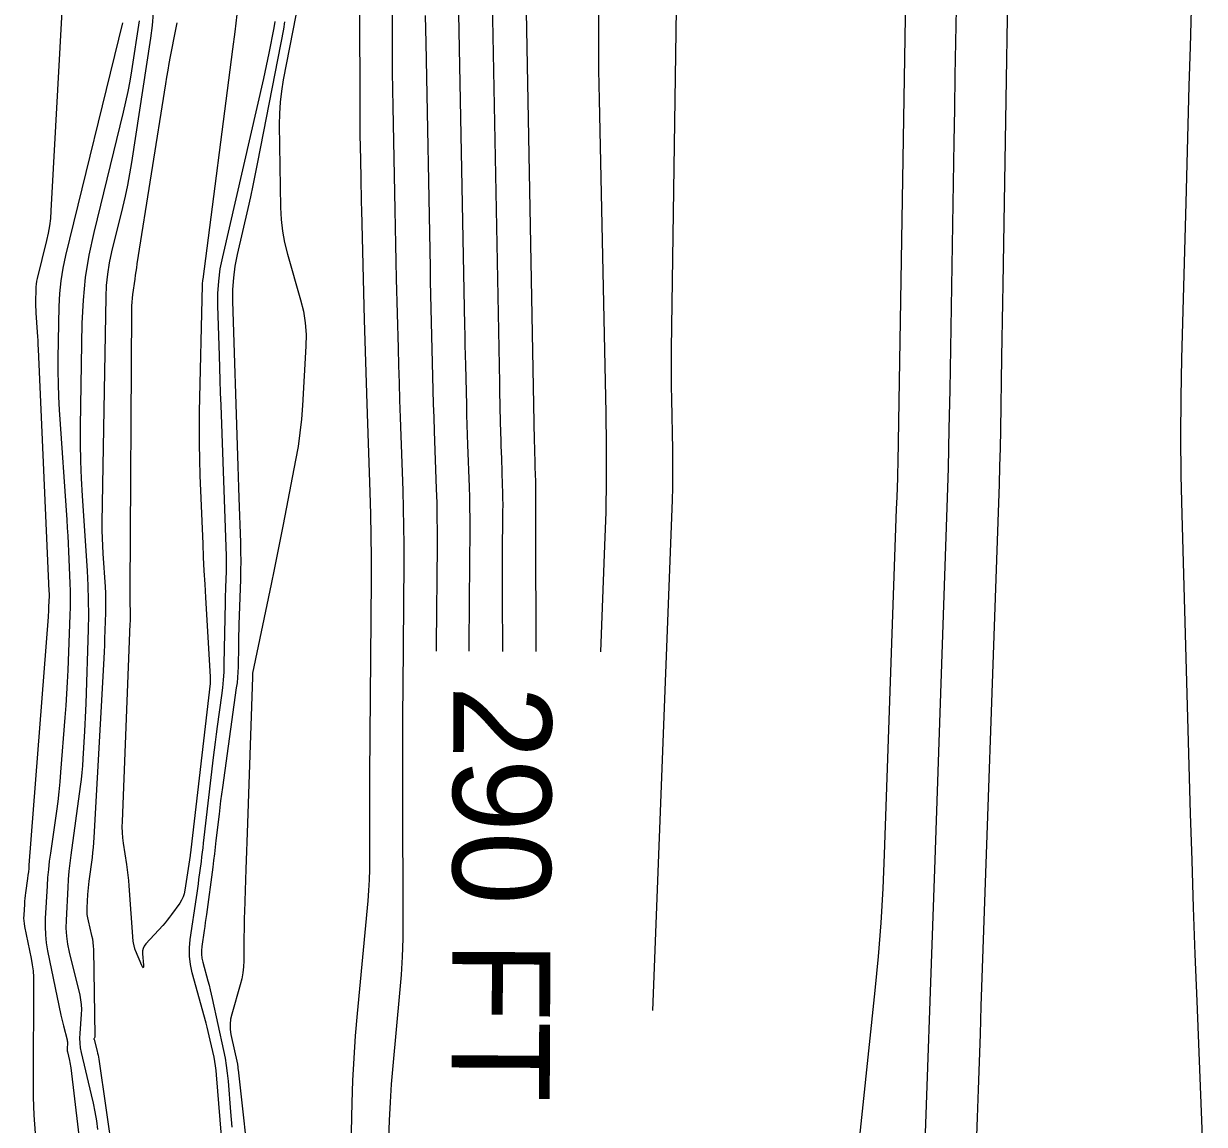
# Model space of a CAD drawing. Extents: x 1768942 to 1774819, y 723037 to 732099.
# Drawn here: x 1770862.5 to 1770934.6, y 724105.6 to 724172.9 of the extents above; entities that cross this region are included whole.
import ezdxf

# ---------------------------------------------------------------- set-up
doc = ezdxf.new("R2010")
doc.units = 0
doc.layers.add('R_Contour Annot', color=7, linetype='Continuous')
doc.layers.add('R_Contours', color=7, linetype='Continuous')

msp = doc.modelspace()

# ---------------------------------------------------------------- linework, layer by layer
at = {"layer": 'R_Contours'}
for points in [[(1770902.56, 724186.241), (1770902.065, 724153.005), (1770902.057, 724152.234), (1770902.056, 724151.462), (1770902.062, 724150.691), (1770902.075, 724149.92), (1770902.14, 724146.835), (1770902.151, 724146.064), (1770902.15, 724145.293), (1770902.138, 724144.522), (1770902.114, 724143.751), (1770900.92, 724112.576)], [(1770922.804, 724185.752), (1770922.328, 724156.942), (1770922.309, 724155.83), (1770922.291, 724154.718), (1770922.273, 724153.606), (1770922.254, 724152.494), (1770922.18, 724148.046), (1770922.158, 724146.934), (1770922.132, 724145.823), (1770922.101, 724144.711), (1770922.065, 724143.6), (1770920.995, 724112.825), (1770920.936, 724111.128), (1770920.877, 724109.431), (1770920.818, 724107.734), (1770920.759, 724106.037), (1770920.523, 724099.249)], [(1770916.552, 724184.367), (1770915.911, 724146.07), (1770915.907, 724145.832), (1770915.901, 724145.594), (1770915.894, 724145.357), (1770915.887, 724145.119), (1770915.845, 724143.931), (1770915.821, 724143.219), (1770915.086, 724122.095), (1770914.996, 724120.014), (1770914.87, 724117.935), (1770914.707, 724115.859), (1770914.509, 724113.785), (1770913.356, 724102.74)], [(1770934.646, 724101.684), (1770934.196, 724113.142), (1770934.087, 724116.007), (1770933.986, 724118.872), (1770933.892, 724121.737), (1770933.806, 724124.603), (1770933.28, 724142.88), (1770933.228, 724145.261), (1770933.21, 724147.642), (1770933.224, 724150.023), (1770933.271, 724152.405), (1770933.527, 724161.931), (1770933.592, 724164.312), (1770933.657, 724166.692), (1770933.722, 724169.073), (1770933.789, 724171.453), (1770934.152, 724184.435)], [(1770893.812, 724134.504), (1770893.787, 724141.931), (1770893.786, 724142.182), (1770893.787, 724142.433), (1770893.788, 724142.684), (1770893.789, 724142.935), (1770893.798, 724144.104), (1770893.799, 724144.272), (1770893.797, 724144.44), (1770893.794, 724144.607), (1770893.789, 724144.775), (1770893.765, 724145.458), (1770893.759, 724145.619), (1770893.754, 724145.781), (1770893.749, 724145.942), (1770893.745, 724146.104), (1770893.729, 724146.751), (1770893.725, 724146.912), (1770893.721, 724147.074), (1770893.718, 724147.235), (1770893.715, 724147.397), (1770893.031, 724183.449)], [(1770891.767, 724134.514), (1770891.756, 724137.881), (1770891.755, 724138.48), (1770891.756, 724139.078), (1770891.758, 724139.677), (1770891.762, 724140.276), (1770891.784, 724143.067), (1770891.785, 724143.467), (1770891.782, 724143.867), (1770891.774, 724144.267), (1770891.762, 724144.667), (1770891.704, 724146.295), (1770891.69, 724146.681), (1770891.678, 724147.066), (1770891.667, 724147.452), (1770891.657, 724147.838), (1770891.618, 724149.38), (1770891.609, 724149.766), (1770891.6, 724150.152), (1770891.592, 724150.537), (1770891.584, 724150.923), (1770891.042, 724179.532)], [(1770884.811, 724104.729), (1770884.847, 724105.845), (1770884.903, 724106.959), (1770884.978, 724108.073), (1770885.072, 724109.185), (1770885.489, 724113.631), (1770885.579, 724114.744), (1770885.643, 724115.857), (1770885.68, 724116.972), (1770885.69, 724118.088), (1770885.664, 724125.732), (1770885.661, 724127.373), (1770885.662, 724129.015), (1770885.668, 724130.657), (1770885.679, 724132.298), (1770885.74, 724139.953), (1770885.743, 724141.051), (1770885.734, 724142.148), (1770885.712, 724143.245), (1770885.679, 724144.342), (1770885.52, 724148.809), (1770885.483, 724149.866), (1770885.45, 724150.924), (1770885.419, 724151.981), (1770885.392, 724153.039), (1770885.286, 724157.27), (1770885.261, 724158.328), (1770885.237, 724159.386), (1770885.214, 724160.443), (1770885.193, 724161.501), (1770885.074, 724167.779), (1770885.056, 724168.848), (1770885.042, 724169.917), (1770885.033, 724170.986), (1770885.029, 724172.055), (1770885.018, 724176.331)], [(1770889.724, 724134.523), (1770889.724, 724134.778), (1770889.724, 724135.724), (1770889.728, 724136.67), (1770889.734, 724137.617), (1770889.769, 724142.029), (1770889.771, 724142.661), (1770889.766, 724143.294), (1770889.753, 724143.926), (1770889.734, 724144.559), (1770889.642, 724147.133), (1770889.621, 724147.743), (1770889.602, 724148.352), (1770889.584, 724148.962), (1770889.568, 724149.571), (1770889.508, 724152.01), (1770889.493, 724152.62), (1770889.479, 724153.23), (1770889.466, 724153.839), (1770889.454, 724154.449), (1770889.053, 724175.614)], [(1770864.838, 724173.993), (1770864.158, 724161.424), (1770864.123, 724160.969), (1770864.066, 724160.517), (1770863.989, 724160.069), (1770863.891, 724159.623), (1770863.322, 724157.3), (1770863.285, 724157.129), (1770863.258, 724156.957), (1770863.24, 724156.784), (1770863.233, 724156.61), (1770863.221, 724155.91), (1770863.22, 724155.735), (1770863.222, 724155.56), (1770863.229, 724155.385), (1770863.238, 724155.21), (1770863.319, 724154.018), (1770863.336, 724153.761), (1770863.351, 724153.504), (1770863.365, 724153.246), (1770863.377, 724152.989), (1770864.04, 724138.186), (1770864.045, 724138.056), (1770864.046, 724137.926), (1770864.045, 724137.796), (1770864.041, 724137.666), (1770864.019, 724137.147), (1770864.013, 724137.017), (1770864.006, 724136.887), (1770863.998, 724136.757), (1770863.988, 724136.628), (1770862.818, 724121.456), (1770862.801, 724121.251), (1770862.78, 724121.047), (1770862.756, 724120.843), (1770862.728, 724120.639), (1770862.602, 724119.759), (1770862.58, 724119.589), (1770862.561, 724119.418), (1770862.545, 724119.247), (1770862.534, 724119.075), (1770862.494, 724118.388), (1770862.49, 724118.216), (1770862.497, 724118.046), (1770862.515, 724117.876), (1770862.544, 724117.707), (1770862.95, 724115.752), (1770863.019, 724115.369), (1770863.068, 724114.984), (1770863.096, 724114.596), (1770863.104, 724114.207), (1770863.072, 724108.368), (1770863.081, 724107.265), (1770863.121, 724106.164), (1770863.191, 724105.065)], [(1770883.017, 724174.231), (1770883.033, 724167.451), (1770883.036, 724166.952), (1770883.04, 724166.454), (1770883.046, 724165.955), (1770883.055, 724165.456), (1770883.093, 724163.461), (1770883.102, 724162.962), (1770883.113, 724162.463), (1770883.124, 724161.965), (1770883.136, 724161.466), (1770883.303, 724154.773), (1770883.337, 724153.491), (1770883.374, 724152.209), (1770883.414, 724150.928), (1770883.459, 724149.646), (1770883.652, 724144.234), (1770883.692, 724142.905), (1770883.718, 724141.575), (1770883.729, 724140.245), (1770883.726, 724138.915), (1770883.63, 724126.94), (1770883.626, 724126.3), (1770883.624, 724125.661), (1770883.623, 724125.021), (1770883.624, 724124.382), (1770883.633, 724121.824), (1770883.627, 724121.184), (1770883.606, 724120.546), (1770883.57, 724119.908), (1770883.518, 724119.271), (1770882.872, 724112.376), (1770882.757, 724111.014), (1770882.665, 724109.65), (1770882.596, 724108.285), (1770882.552, 724106.919), (1770882.276, 724095.421)], [(1770870.417, 724173.538), (1770870.339, 724172.756), (1770870.234, 724171.977), (1770869.075, 724164.382), (1770868.962, 724163.693), (1770868.834, 724163.008), (1770868.691, 724162.326), (1770868.532, 724161.646), (1770867.868, 724158.935), (1770867.721, 724158.255), (1770867.613, 724157.57), (1770867.544, 724156.88), (1770867.512, 724156.184), (1770867.28, 724142.382), (1770867.277, 724141.91), (1770867.284, 724141.438), (1770867.301, 724140.967), (1770867.328, 724140.496), (1770867.465, 724138.462), (1770867.487, 724138.066), (1770867.499, 724137.67), (1770867.501, 724137.273), (1770867.493, 724136.876), (1770867.441, 724135.289), (1770867.426, 724134.892), (1770867.41, 724134.495), (1770867.392, 724134.099), (1770867.371, 724133.702), (1770866.789, 724123.148), (1770866.769, 724122.838), (1770866.742, 724122.528), (1770866.709, 724122.219), (1770866.67, 724121.911), (1770866.472, 724120.465), (1770866.446, 724120.264), (1770866.425, 724120.062), (1770866.408, 724119.859), (1770866.395, 724119.656), (1770866.354, 724118.844), (1770866.351, 724118.642), (1770866.363, 724118.441), (1770866.389, 724118.241), (1770866.43, 724118.043), (1770866.646, 724117.158), (1770866.692, 724116.944), (1770866.726, 724116.728), (1770866.748, 724116.51), (1770866.758, 724116.292), (1770866.849, 724111.024), (1770866.848, 724111.004), (1770866.845, 724110.983), (1770866.84, 724110.963), (1770866.833, 724110.944), (1770866.798, 724110.867), (1770866.792, 724110.848), (1770866.788, 724110.828), (1770866.788, 724110.808), (1770866.792, 724110.788), (1770866.978, 724110.087), (1770867.009, 724109.963), (1770867.037, 724109.838), (1770867.06, 724109.713), (1770867.08, 724109.586), (1770868.364, 724100.671)], [(1770875.516, 724173.432), (1770875.395, 724172.37), (1770875.263, 724171.309), (1770873.439, 724157.266), (1770873.435, 724157.235), (1770873.431, 724157.204), (1770873.426, 724157.173), (1770873.422, 724157.142), (1770873.403, 724157.018), (1770873.399, 724156.987), (1770873.396, 724156.955), (1770873.394, 724156.924), (1770873.393, 724156.893), (1770873.228, 724149.148), (1770873.215, 724148.177), (1770873.217, 724147.206), (1770873.234, 724146.236), (1770873.266, 724145.266), (1770873.436, 724141.087), (1770873.472, 724140.266), (1770873.511, 724139.445), (1770873.554, 724138.624), (1770873.602, 724137.804), (1770873.894, 724132.949), (1770873.896, 724132.915), (1770873.897, 724132.881), (1770873.898, 724132.848), (1770873.897, 724132.814), (1770873.894, 724132.62), (1770873.893, 724132.61), (1770873.892, 724132.599), (1770873.888, 724132.574), (1770873.886, 724132.558), (1770872.711, 724122.385), (1770872.707, 724122.356), (1770872.704, 724122.328), (1770872.7, 724122.299), (1770872.696, 724122.27), (1770872.681, 724122.155), (1770872.677, 724122.126), (1770872.673, 724122.098), (1770872.669, 724122.069), (1770872.665, 724122.04), (1770872.346, 724119.912), (1770872.302, 724119.704), (1770872.235, 724119.505), (1770872.145, 724119.316), (1770872.031, 724119.136), (1770871.529, 724118.437), (1770871.402, 724118.264), (1770871.269, 724118.095), (1770871.131, 724117.93), (1770870.988, 724117.769), (1770869.959, 724116.641), (1770869.858, 724116.507), (1770869.791, 724116.363), (1770869.756, 724116.206), (1770869.754, 724116.039), (1770869.813, 724115.347), (1770869.818, 724115.216), (1770869.802, 724115.168), (1770869.766, 724115.203), (1770869.71, 724115.322), (1770869.33, 724116.24), (1770869.312, 724116.286), (1770869.296, 724116.332), (1770869.281, 724116.379), (1770869.268, 724116.427), (1770869.219, 724116.618), (1770869.208, 724116.666), (1770869.199, 724116.714), (1770869.192, 724116.763), (1770869.187, 724116.812), (1770868.942, 724120.177), (1770868.915, 724120.506), (1770868.881, 724120.835), (1770868.841, 724121.163), (1770868.795, 724121.49), (1770868.596, 724122.798), (1770868.555, 724123.125), (1770868.529, 724123.453), (1770868.518, 724123.782), (1770868.524, 724124.112), (1770869.008, 724136.189), (1770869.014, 724136.359), (1770869.017, 724136.529), (1770869.017, 724136.699), (1770869.015, 724136.869), (1770869.001, 724137.55), (1770868.998, 724137.72), (1770868.997, 724137.891), (1770868.996, 724138.061), (1770868.996, 724138.231), (1770869.103, 724155.386), (1770869.108, 724155.621), (1770869.121, 724155.856), (1770869.142, 724156.091), (1770869.17, 724156.325), (1770869.299, 724157.26), (1770869.331, 724157.494), (1770869.365, 724157.727), (1770869.4, 724157.96), (1770869.437, 724158.193), (1770871.176, 724169.195), (1770871.244, 724169.611), (1770871.315, 724170.027), (1770871.391, 724170.442), (1770871.47, 724170.856), (1770871.796, 724172.51), (1770871.864, 724172.925)], [(1770879.127, 724173.394), (1770878.357, 724169.431), (1770878.243, 724168.751), (1770878.164, 724168.069), (1770878.121, 724167.383), (1770878.114, 724166.694), (1770878.19, 724161.636), (1770878.225, 724160.914), (1770878.307, 724160.199), (1770878.437, 724159.491), (1770878.614, 724158.79), (1770879.42, 724156), (1770879.591, 724155.3), (1770879.701, 724154.592), (1770879.75, 724153.878), (1770879.739, 724153.156), (1770879.531, 724149.545), (1770879.468, 724148.703), (1770879.378, 724147.865), (1770879.259, 724147.03), (1770879.113, 724146.199), (1770878.354, 724142.265), (1770878.175, 724141.351), (1770877.993, 724140.437), (1770877.807, 724139.524), (1770877.618, 724138.612), (1770876.48, 724133.185), (1770876.476, 724133.164), (1770876.474, 724133.143), (1770876.473, 724133.121), (1770876.474, 724133.1), (1770876.48, 724133.014), (1770876.481, 724132.993), (1770876.482, 724132.971), (1770876.482, 724132.95), (1770876.482, 724132.928), (1770876.153, 724123.429), (1770876.134, 724122.871), (1770876.114, 724122.314), (1770876.095, 724121.756), (1770876.076, 724121.198), (1770875.987, 724118.603), (1770875.976, 724118.228), (1770875.967, 724117.853), (1770875.96, 724117.478), (1770875.956, 724117.103), (1770875.944, 724115.603), (1770875.928, 724115.23), (1770875.887, 724114.861), (1770875.82, 724114.495), (1770875.728, 724114.133), (1770875.206, 724112.344), (1770875.136, 724112.036), (1770875.106, 724111.726), (1770875.115, 724111.415), (1770875.163, 724111.103), (1770875.557, 724109.282), (1770875.563, 724109.254), (1770875.568, 724109.226), (1770875.571, 724109.197), (1770875.574, 724109.169), (1770875.583, 724109.056), (1770875.586, 724109.027), (1770875.588, 724108.999), (1770875.591, 724108.971), (1770875.594, 724108.942), (1770876.364, 724102.132)], [(1770887.038, 724173.38), (1770887.049, 724172.538), (1770887.063, 724171.697), (1770887.324, 724157.975), (1770887.34, 724157.141), (1770887.358, 724156.308), (1770887.377, 724155.474), (1770887.397, 724154.64), (1770887.48, 724151.305), (1770887.502, 724150.472), (1770887.526, 724149.638), (1770887.552, 724148.804), (1770887.581, 724147.971), (1770887.707, 724144.45), (1770887.733, 724143.586), (1770887.75, 724142.721), (1770887.757, 724141.856), (1770887.755, 724140.991), (1770887.707, 724134.957), (1770887.704, 724134.533)], [(1770897.618, 724173.636), (1770897.615, 724171.835), (1770897.629, 724170.034), (1770897.659, 724168.232), (1770898.066, 724149.092), (1770898.094, 724147.065), (1770898.092, 724145.038), (1770898.06, 724143.011), (1770897.997, 724140.984), (1770897.748, 724134.486)], [(1770917.45, 724100.476), (1770918.191, 724121.776), (1770918.274, 724124.169), (1770918.357, 724126.562), (1770918.44, 724128.956), (1770918.523, 724131.349), (1770918.856, 724140.922), (1770918.934, 724143.315), (1770919.001, 724145.709), (1770919.057, 724148.103), (1770919.103, 724150.497), (1770919.356, 724165.641), (1770919.39, 724167.675), (1770919.424, 724169.71), (1770919.458, 724171.745), (1770919.492, 724173.78)], [(1770868.533, 724172.93), (1770865.047, 724158.7), (1770864.881, 724157.93), (1770864.758, 724157.155), (1770864.679, 724156.374), (1770864.644, 724155.588), (1770864.591, 724152.431), (1770864.586, 724151.642), (1770864.598, 724150.853), (1770864.626, 724150.065), (1770864.671, 724149.277), (1770865.126, 724142.553), (1770865.157, 724142.068), (1770865.186, 724141.583), (1770865.212, 724141.098), (1770865.235, 724140.613), (1770865.322, 724138.672), (1770865.338, 724138.186), (1770865.344, 724137.701), (1770865.339, 724137.215), (1770865.324, 724136.73), (1770865.183, 724133.364), (1770865.149, 724132.641), (1770865.109, 724131.919), (1770865.063, 724131.197), (1770865.011, 724130.476), (1770864.753, 724127.128), (1770864.702, 724126.532), (1770864.641, 724125.937), (1770864.571, 724125.343), (1770864.491, 724124.75), (1770864.124, 724122.188), (1770864.059, 724121.691), (1770864.004, 724121.194), (1770863.959, 724120.695), (1770863.925, 724120.195), (1770863.81, 724118.193), (1770863.798, 724117.694), (1770863.818, 724117.197), (1770863.871, 724116.703), (1770863.956, 724116.211), (1770864.771, 724112.279), (1770864.806, 724112.115), (1770864.843, 724111.951), (1770864.882, 724111.788), (1770864.923, 724111.626), (1770865.144, 724110.772), (1770865.157, 724110.712), (1770865.165, 724110.652), (1770865.168, 724110.591), (1770865.166, 724110.53), (1770865.147, 724110.285), (1770865.144, 724110.224), (1770865.147, 724110.163), (1770865.154, 724110.102), (1770865.166, 724110.042), (1770865.294, 724109.506), (1770865.318, 724109.396), (1770865.34, 724109.286), (1770865.358, 724109.175), (1770865.373, 724109.064), (1770867.028, 724095.119)], [(1770869.543, 724173.044), (1770869.076, 724169.985), (1770868.972, 724169.351), (1770868.854, 724168.72), (1770868.722, 724168.092), (1770868.576, 724167.467), (1770866.771, 724160.1), (1770866.476, 724158.731), (1770866.259, 724157.353), (1770866.119, 724155.965), (1770866.056, 724154.566), (1770865.95, 724148.275), (1770865.943, 724147.21), (1770865.959, 724146.146), (1770865.997, 724145.083), (1770866.058, 724144.02), (1770866.368, 724139.432), (1770866.417, 724138.537), (1770866.444, 724137.643), (1770866.448, 724136.748), (1770866.43, 724135.853), (1770866.282, 724131.325), (1770866.267, 724130.903), (1770866.25, 724130.48), (1770866.23, 724130.058), (1770866.208, 724129.636), (1770866.115, 724127.948), (1770866.087, 724127.526), (1770866.051, 724127.105), (1770866.006, 724126.685), (1770865.953, 724126.266), (1770865.375, 724122.062), (1770865.313, 724121.569), (1770865.261, 724121.075), (1770865.22, 724120.58), (1770865.189, 724120.084), (1770865.088, 724118.098), (1770865.08, 724117.604), (1770865.109, 724117.112), (1770865.173, 724116.624), (1770865.273, 724116.14), (1770865.917, 724113.505), (1770865.975, 724113.217), (1770866.011, 724112.928), (1770866.023, 724112.636), (1770866.012, 724112.342), (1770865.921, 724111.165), (1770865.91, 724110.871), (1770865.921, 724110.579), (1770865.956, 724110.289), (1770866.013, 724110.001), (1770866.628, 724107.424), (1770866.745, 724106.897), (1770866.847, 724106.368), (1770866.934, 724105.836), (1770867.006, 724105.301)], [(1770874.786, 724102.39), (1770874.283, 724108.645), (1770874.257, 724108.912), (1770874.222, 724109.178), (1770874.178, 724109.443), (1770874.126, 724109.707), (1770873.898, 724110.759), (1770873.839, 724111.021), (1770873.776, 724111.283), (1770873.71, 724111.544), (1770873.64, 724111.804), (1770872.792, 724114.867), (1770872.68, 724115.373), (1770872.621, 724115.883), (1770872.617, 724116.397), (1770872.668, 724116.913), (1770873.051, 724119.472), (1770873.092, 724119.748), (1770873.132, 724120.024), (1770873.17, 724120.3), (1770873.207, 724120.577), (1770873.354, 724121.683), (1770873.39, 724121.96), (1770873.424, 724122.236), (1770873.458, 724122.513), (1770873.491, 724122.79), (1770874.096, 724128.024), (1770874.152, 724128.499), (1770874.211, 724128.974), (1770874.273, 724129.448), (1770874.338, 724129.922), (1770874.604, 724131.818), (1770874.663, 724132.292), (1770874.708, 724132.767), (1770874.738, 724133.244), (1770874.754, 724133.722), (1770874.825, 724137.493), (1770874.83, 724137.73), (1770874.836, 724137.967), (1770874.842, 724138.204), (1770874.85, 724138.441), (1770874.881, 724139.388), (1770874.887, 724139.625), (1770874.888, 724139.862), (1770874.886, 724140.099), (1770874.88, 724140.336), (1770874.557, 724149.56), (1770874.53, 724150.319), (1770874.505, 724151.078), (1770874.48, 724151.838), (1770874.456, 724152.597), (1770874.361, 724155.633), (1770874.362, 724156.39), (1770874.411, 724157.142), (1770874.508, 724157.89), (1770874.655, 724158.632), (1770877.165, 724169.529), (1770877.252, 724169.913), (1770877.335, 724170.298), (1770877.415, 724170.683), (1770877.492, 724171.07), (1770877.793, 724172.616), (1770877.855, 724173.004)], [(1770878.441, 724172.988), (1770878.368, 724172.53), (1770876.788, 724164.403), (1770876.647, 724163.695), (1770876.5, 724162.988), (1770876.347, 724162.283), (1770876.188, 724161.578), (1770875.54, 724158.764), (1770875.401, 724158.058), (1770875.308, 724157.348), (1770875.261, 724156.633), (1770875.261, 724155.913), (1770875.556, 724146.467), (1770875.576, 724145.823), (1770875.598, 724145.179), (1770875.619, 724144.536), (1770875.641, 724143.892), (1770875.737, 724141.157), (1770875.752, 724140.593), (1770875.758, 724140.029), (1770875.753, 724139.465), (1770875.74, 724138.901), (1770875.65, 724136.165), (1770875.639, 724135.84), (1770875.63, 724135.516), (1770875.623, 724135.192), (1770875.616, 724134.867), (1770875.592, 724133.569), (1770875.581, 724133.245), (1770875.56, 724132.922), (1770875.53, 724132.599), (1770875.489, 724132.278), (1770874.636, 724126.187), (1770874.581, 724125.784), (1770874.528, 724125.38), (1770874.478, 724124.976), (1770874.43, 724124.572), (1770874.243, 724122.954), (1770874.195, 724122.549), (1770874.146, 724122.145), (1770874.095, 724121.741), (1770874.043, 724121.337), (1770873.659, 724118.438), (1770873.626, 724118.194), (1770873.592, 724117.949), (1770873.557, 724117.705), (1770873.521, 724117.462), (1770873.375, 724116.486), (1770873.351, 724116.243), (1770873.353, 724116.002), (1770873.381, 724115.762), (1770873.434, 724115.524), (1770873.75, 724114.379), (1770873.823, 724114.109), (1770873.892, 724113.837), (1770873.957, 724113.565), (1770874.019, 724113.292), (1770874.704, 724110.129), (1770874.797, 724109.665), (1770874.874, 724109.199), (1770874.935, 724108.73), (1770874.981, 724108.26), (1770875.133, 724106.373), (1770875.172, 724105.901), (1770875.216, 724105.43)]]:
    msp.add_lwpolyline(points, dxfattribs=at)

# ---------------------------------------------------------------- texts
at = {"layer": 'R_Contour Annot'}
msp.add_text('290 FT', height=6, rotation=269.73259, dxfattribs=at).set_placement((1770888.758, 724132.425))

doc.saveas('drawing.dxf')
